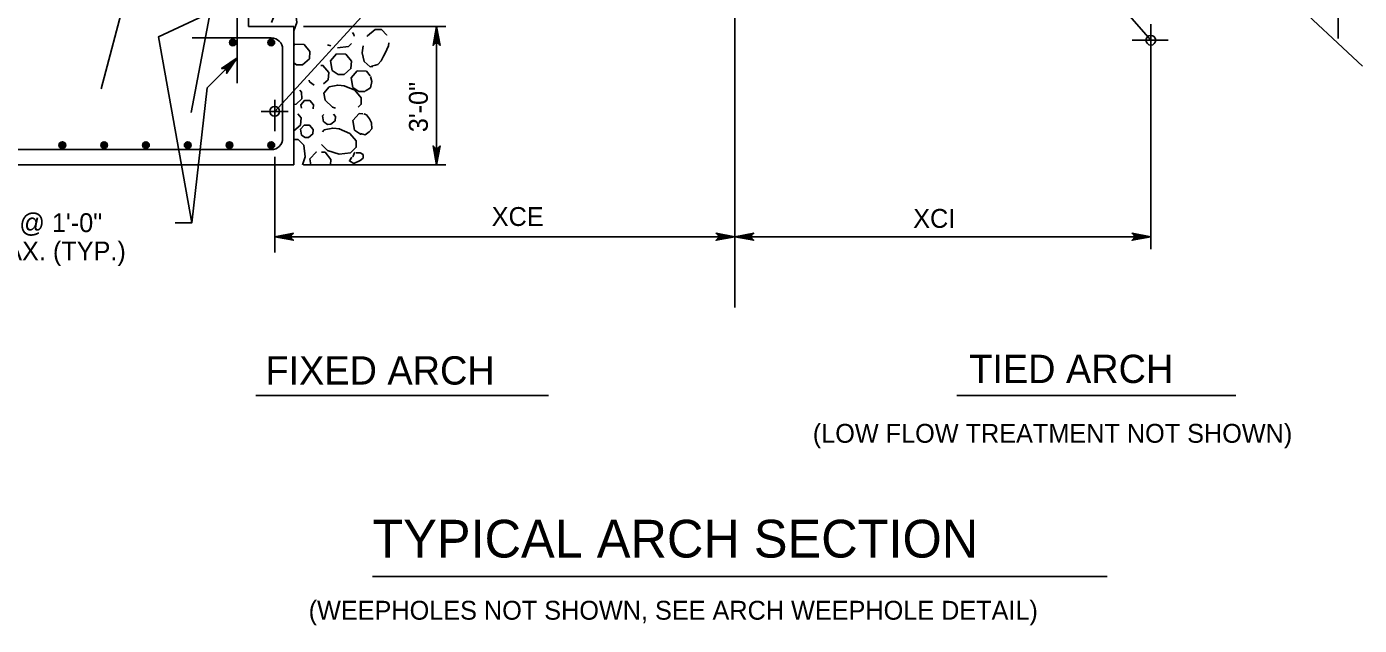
# Model space of a CAD drawing. Extents: x 639028 to 639883, y 298843 to 300031.
# Drawn here: x 639218 to 639429.9, y 299744.1 to 299839.2 of the extents above; entities that cross this region are included whole.
import ezdxf

# ---------------------------------------------------------------- set-up
doc = ezdxf.new("R2010")
doc.units = 0
for name, color, linetype in [('1', 7, 'Continuous'), ('2', 7, 'Continuous'), ('52', 7, 'Continuous'), ('53', 7, 'Continuous'), ('56', 7, 'Continuous')]:
    doc.layers.add(name, color=color, linetype=linetype)

# ---------------------------------------------------------------- blocks, each defined once
blk = doc.blocks.new('LT')
at = {"layer": '1'}
blk.add_lwpolyline([(0, 0), (-11.18, -2.1), (-10.75, -1.8), (-10.32, -1.5), (-10.1, -1.12), (-9.88, -0.75), (-9.81, -0.38), (-9.75, 0), (-9.81, 0.38), (-9.88, 0.75), (-10.1, 1.12), (-10.32, 1.5), (-10.75, 1.8), (-11.18, 2.1), (0, 0), (-10.75, 1.8), (-10.32, 1.5), (0, 0), (-10.1, 1.12), (-9.88, 0.75), (0, 0), (-9.81, 0.38), (-9.75, 0), (0, 0), (-9.81, -0.38), (-9.88, -0.75), (0, 0), (-10.1, -1.12), (-10.32, -1.5), (0, 0), (-10.75, -1.8)], dxfattribs=at)

msp = doc.modelspace()

# ---------------------------------------------------------------- linework, layer by layer
at = {"layer": '2'}
for p, q in [((639330.61, 299794.59), (639330.61, 299970.2)), ((639372.87, 299951.85), (639257.47, 299825.76)), ((639396.72, 299837.08), (639300.36, 299947.2)), ((639240.43, 299869.31), (639229.89, 299829.34)), ((639251.7, 299864.92), (639244.16, 299825.57)), ((639253.32, 299864.92), (639253.32, 299839.24)), ((639251.52, 299861.44), (639251.52, 299830.24)), ((639408.49, 299853.45), (639430.36, 299832.95)), ((639426.49, 299844.95), (639426.49, 299837.33)), ((639253.32, 299839.24), (639260.52, 299839.24)), ((639260.52, 299839.24), (639260.52, 299817.28)), ((639396.72, 299803.85), (639396.72, 299839.61)), ((639244.32, 299837.44), (639256.92, 299837.44)), ((639393.74, 299837.08), (639399.49, 299837.08)), ((639396.74, 299837.08), (639394.74, 299837.08)), ((639258.72, 299835.64), (639258.72, 299821.48)), ((639257.47, 299822.62), (639257.47, 299827.62)), ((639255.29, 299825.76), (639259.63, 299825.76)), ((639256.92, 299819.68), (639197.15, 299819.68)), ((639260.52, 299817.28), (639193.55, 299817.28)), ((639257.47, 299803.33), (639257.47, 299818.54)), ((639257.47, 299805.84), (639330.61, 299805.84)), ((639330.61, 299805.84), (639396.72, 299805.84))]:
    msp.add_line(p, q, dxfattribs=at)
for centre, radius in [((639250.8, 299836.72), 0.533), ((639250.8, 299836.72), 0.4), ((639250.8, 299836.72), 0.267), ((639250.8, 299836.72), 0.133), ((639256.92, 299836.72), 0.533), ((639256.92, 299836.72), 0.4), ((639256.92, 299836.72), 0.267), ((639256.92, 299836.72), 0.133), ((639396.72, 299837.08), 0.773), ((639257.47, 299825.76), 0.773), ((639223.71, 299820.4), 0.533), ((639223.71, 299820.4), 0.4), ((639223.71, 299820.4), 0.267), ((639223.71, 299820.4), 0.133), ((639230.35, 299820.4), 0.533), ((639230.35, 299820.4), 0.4), ((639230.35, 299820.4), 0.267), ((639230.35, 299820.4), 0.133), ((639237, 299820.4), 0.533), ((639237, 299820.4), 0.4), ((639237, 299820.4), 0.267), ((639237, 299820.4), 0.133), ((639243.64, 299820.4), 0.533), ((639243.64, 299820.4), 0.4), ((639243.64, 299820.4), 0.267), ((639243.64, 299820.4), 0.133), ((639250.28, 299820.4), 0.533), ((639250.28, 299820.4), 0.4), ((639250.28, 299820.4), 0.267), ((639250.28, 299820.4), 0.133), ((639256.92, 299820.4), 0.533), ((639256.92, 299820.4), 0.4), ((639256.92, 299820.4), 0.267), ((639256.92, 299820.4), 0.133)]:
    msp.add_circle(centre, radius, dxfattribs=at)
for centre, start, end in [((639256.92, 299835.64), 0, 90), ((639256.92, 299821.48), 270, 0)]:
    msp.add_arc(centre, 1.8, start, end, dxfattribs=at)
at = {"layer": '52'}
for p, q in [((639262.02, 299839.24), (639284.69, 299839.24)), ((639283.19, 299817.28), (639283.19, 299839.24)), ((639262.02, 299817.28), (639284.69, 299817.28))]:
    msp.add_line(p, q, dxfattribs=at)
for points in [[(639249.35, 299842.46), (639238.99, 299837.59), (639244.27, 299808.02)], [(639251.52, 299834.29), (639246.73, 299829.49), (639244.27, 299808.02), (639241.63, 299808.02)], [(639251.52, 299834.29), (639249.81, 299831.79), (639249.83, 299831.92), (639249.86, 299832.06), (639249.83, 299832.17), (639249.8, 299832.29), (639249.74, 299832.37), (639249.68, 299832.45), (639249.6, 299832.51), (639249.52, 299832.57), (639249.4, 299832.6), (639249.29, 299832.63), (639249.15, 299832.6), (639249.02, 299832.58), (639251.52, 299834.29), (639249.15, 299832.6), (639249.29, 299832.63), (639251.52, 299834.29), (639249.4, 299832.6), (639249.52, 299832.57), (639251.52, 299834.29), (639249.6, 299832.51), (639249.68, 299832.45), (639251.52, 299834.29), (639249.74, 299832.37), (639249.8, 299832.29), (639251.52, 299834.29), (639249.83, 299832.17), (639249.86, 299832.06), (639251.52, 299834.29), (639249.83, 299831.92)], [(639257.47, 299805.84), (639260.45, 299806.4), (639260.34, 299806.32), (639260.22, 299806.24), (639260.16, 299806.14), (639260.1, 299806.04), (639260.09, 299805.94), (639260.07, 299805.84), (639260.09, 299805.74), (639260.1, 299805.64), (639260.16, 299805.54), (639260.22, 299805.44), (639260.34, 299805.36), (639260.45, 299805.28), (639257.47, 299805.84), (639260.34, 299805.36), (639260.22, 299805.44), (639257.47, 299805.84), (639260.16, 299805.54), (639260.1, 299805.64), (639257.47, 299805.84), (639260.09, 299805.74), (639260.07, 299805.84), (639257.47, 299805.84), (639260.09, 299805.94), (639260.1, 299806.04), (639257.47, 299805.84), (639260.16, 299806.14), (639260.22, 299806.24), (639257.47, 299805.84), (639260.34, 299806.32)], [(639330.61, 299805.84), (639327.63, 299805.28), (639327.75, 299805.36), (639327.86, 299805.44), (639327.92, 299805.54), (639327.98, 299805.64), (639328, 299805.74), (639328.01, 299805.84), (639328, 299805.94), (639327.98, 299806.04), (639327.92, 299806.14), (639327.86, 299806.24), (639327.75, 299806.32), (639327.63, 299806.4), (639330.61, 299805.84), (639327.75, 299806.32), (639327.86, 299806.24), (639330.61, 299805.84), (639327.92, 299806.14), (639327.98, 299806.04), (639330.61, 299805.84), (639328, 299805.94), (639328.01, 299805.84), (639330.61, 299805.84), (639328, 299805.74), (639327.98, 299805.64), (639330.61, 299805.84), (639327.92, 299805.54), (639327.86, 299805.44), (639330.61, 299805.84), (639327.75, 299805.36)], [(639330.61, 299805.84), (639333.6, 299806.4), (639333.48, 299806.32), (639333.37, 299806.24), (639333.31, 299806.14), (639333.25, 299806.04), (639333.23, 299805.94), (639333.21, 299805.84), (639333.23, 299805.74), (639333.25, 299805.64), (639333.31, 299805.54), (639333.37, 299805.44), (639333.48, 299805.36), (639333.6, 299805.28), (639330.61, 299805.84), (639333.48, 299805.36), (639333.37, 299805.44), (639330.61, 299805.84), (639333.31, 299805.54), (639333.25, 299805.64), (639330.61, 299805.84), (639333.23, 299805.74), (639333.21, 299805.84), (639330.61, 299805.84), (639333.23, 299805.94), (639333.25, 299806.04), (639330.61, 299805.84), (639333.31, 299806.14), (639333.37, 299806.24), (639330.61, 299805.84), (639333.48, 299806.32)], [(639396.72, 299805.84), (639393.74, 299805.28), (639393.86, 299805.36), (639393.97, 299805.44), (639394.03, 299805.54), (639394.09, 299805.64), (639394.11, 299805.74), (639394.12, 299805.84), (639394.11, 299805.94), (639394.09, 299806.04), (639394.03, 299806.14), (639393.97, 299806.24), (639393.86, 299806.32), (639393.74, 299806.4), (639396.72, 299805.84), (639393.86, 299806.32), (639393.97, 299806.24), (639396.72, 299805.84), (639394.03, 299806.14), (639394.09, 299806.04), (639396.72, 299805.84), (639394.11, 299805.94), (639394.12, 299805.84), (639396.72, 299805.84), (639394.11, 299805.74), (639394.09, 299805.64), (639396.72, 299805.84), (639394.03, 299805.54), (639393.97, 299805.44), (639396.72, 299805.84), (639393.86, 299805.36)]]:
    msp.add_lwpolyline(points, dxfattribs=at)
at = {"layer": '53'}
for p, q in [((639254.49, 299780.58), (639300.99, 299780.58)), ((639365.86, 299780.58), (639410.24, 299780.58)), ((639272.99, 299751.83), (639389.78, 299751.83))]:
    msp.add_line(p, q, dxfattribs=at)
at = {"layer": '56'}
for points in [[(639256.93, 299839.92), (639257.65, 299841.6), (639258.85, 299842.61), (639259.87, 299842.63), (639260.75, 299841.72), (639260.97, 299839.91), (639260.52, 299838.55)], [(639269.82, 299838.28), (639270.06, 299837.98), (639270.07, 299837.71)], [(639272.18, 299837.68), (639272.21, 299837.75), (639273.41, 299838.76), (639274.43, 299838.79), (639275.31, 299837.88), (639275.31, 299837.86)], [(639260.52, 299836.26), (639260.69, 299836.45), (639262.14, 299836.42), (639263.07, 299835.29), (639262.97, 299834.13), (639261.88, 299833.19), (639260.94, 299833.17), (639260.52, 299833.46)], [(639266.37, 299836.19), (639265.83, 299836.37)], [(639269.66, 299836.55), (639269.18, 299836.08), (639267.45, 299835.87)], [(639273.07, 299832.92), (639272.66, 299832.85), (639271.68, 299833.71), (639271.38, 299835.07), (639271.5, 299836.16)], [(639275.63, 299836.66), (639275.55, 299836.19), (639275.01, 299835.03), (639274.78, 299834.56), (639274.39, 299833.79), (639273.84, 299833.24), (639273.46, 299833.09), (639272.83, 299832.93)], [(639266.6, 299832.27), (639266.33, 299833.82), (639267.3, 299834.91), (639268.75, 299834.88), (639269.68, 299833.74), (639269.58, 299832.58), (639268.49, 299831.64), (639267.55, 299831.63), (639266.61, 299832.27)], [(639264.82, 299833.08), (639265.13, 299833.07), (639266.06, 299831.94), (639265.96, 299830.78), (639265.22, 299830.14)], [(639269.89, 299829.55), (639269.62, 299831.11), (639270.59, 299832.19), (639272.04, 299832.16), (639272.63, 299831.44)], [(639262.99, 299830.46), (639262.94, 299830.72)], [(639263.76, 299829.94), (639262.99, 299830.46)], [(639267.15, 299826.25), (639266.65, 299826.42), (639265.47, 299827.56), (639265.28, 299828.67), (639266.14, 299829.66), (639267.49, 299829.95), (639268.58, 299829.83)], [(639268.5, 299829.85), (639270.18, 299829.13), (639271.19, 299827.93), (639271.21, 299826.9), (639270.74, 299826.45)], [(639272.7, 299831.33), (639272.91, 299830.53), (639272.68, 299829.53), (639272.02, 299829.07), (639272.17, 299829.22)], [(639261.44, 299829.15), (639261.74, 299828.8), (639261.76, 299827.78), (639260.85, 299826.9), (639260.52, 299826.86)], [(639271.94, 299829.07), (639271.78, 299828.93), (639270.84, 299828.91), (639269.89, 299829.55)], [(639261.72, 299826.26), (639261.62, 299826.83), (639262.2, 299827.48), (639263.07, 299827.47), (639263.63, 299826.78), (639263.58, 299826.19)], [(639270.17, 299822.77), (639269.9, 299824.32), (639270.87, 299825.41), (639271.47, 299825.39)], [(639261.15, 299825.36), (639261.66, 299824.74), (639261.55, 299823.58), (639260.52, 299822.68)], [(639261.72, 299821.99), (639261.56, 299822.92), (639262.14, 299823.57), (639263.01, 299823.55), (639263.57, 299822.87), (639263.51, 299822.18), (639262.85, 299821.61), (639262.29, 299821.6), (639261.72, 299821.99)], [(639265.24, 299824.12), (639265.07, 299825.05), (639265.25, 299825.25)], [(639266.82, 299825.33), (639267.12, 299824.97), (639267.06, 299824.27), (639266.4, 299823.71), (639265.84, 299823.7), (639265.27, 299824.08)], [(639271.65, 299825.36), (639272.04, 299825.21), (639272.52, 299824.56), (639272.83, 299823.94), (639272.91, 299823.01), (639272.46, 299822.52), (639271.84, 299822.05), (639271.12, 299822.23)], [(639260.52, 299821.27), (639261.22, 299821.29), (639262.1, 299820.38), (639262.32, 299818.56), (639261.89, 299817.28)], [(639267.71, 299823), (639269.38, 299822.27), (639270.39, 299821.07), (639270.42, 299820.05), (639269.51, 299819.17), (639267.69, 299818.95), (639265.85, 299819.57), (639264.91, 299820.48)], [(639265.06, 299822.49), (639265.34, 299822.81), (639266.7, 299823.1), (639267.79, 299822.98)], [(639271.22, 299822.13), (639271.12, 299822.13), (639270.17, 299822.77)], [(639263.23, 299817.28), (639263.06, 299818.22), (639264.03, 299819.3), (639264.09, 299819.3)], [(639264.9, 299819.29), (639265.48, 299819.28), (639266.41, 299818.14), (639266.33, 299817.28)], [(639270.43, 299819.2), (639271.05, 299819.2), (639271.51, 299818.89), (639271.51, 299818.35), (639271.05, 299817.96), (639270.04, 299817.49), (639269.34, 299817.88), (639269.73, 299818.5)], [(639269.86, 299818.54), (639270.13, 299819.17), (639270.27, 299819.29)]]:
    msp.add_lwpolyline(points, dxfattribs=at)

# ---------------------------------------------------------------- block references
at = {"layer": '52', "xscale": 0.2682193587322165, "yscale": 0.26822435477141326}
for p, rotation in [((639283.19, 299839.24), 90), ((639283.19, 299817.28), -90)]:
    msp.add_blockref('LT', p, dxfattribs=dict(at, rotation=rotation))

# ---------------------------------------------------------------- texts
at = {"layer": '2'}
for s, p in [('XCE', (639291.96, 299807.55)), ('#5 @ 1\'-0"', (639211.29, 299806.57)), ('XCI', (639358.95, 299807.25)), ('MAX. (TYP.)', (639211.29, 299802.07)), ('(LOW FLOW TREATMENT NOT SHOWN)', (639342.99, 299773.08)), ('(WEEPHOLES NOT SHOWN, SEE ARCH WEEPHOLE DETAIL)', (639262.86, 299744.95))]:
    msp.add_text(s, height=3, dxfattribs=at).set_placement(p)
at = {"layer": '52'}
msp.add_text('3\'-0"', height=3, rotation=90, dxfattribs=at).set_placement((639281.8, 299822.46))
at = {"layer": '53'}
for s, height, p in [('FIXED ARCH', 4.5, (639255.99, 299782.33)), ('TIED ARCH', 4.5, (639367.86, 299782.58)), ('TYPICAL ARCH SECTION', 6, (639272.99, 299754.83))]:
    msp.add_text(s, height=height, dxfattribs=at).set_placement(p)

doc.saveas('drawing.dxf')
